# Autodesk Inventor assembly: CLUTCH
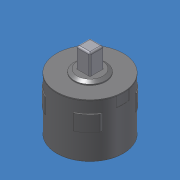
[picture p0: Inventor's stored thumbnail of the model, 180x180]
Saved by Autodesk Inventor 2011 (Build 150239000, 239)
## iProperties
Created: 2007-08
Part Number: CLUTCH
Document SubType Name: Assembly
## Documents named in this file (3)
- C:\Data Folder\VEX 2011\Inventor Datasets\Unit 6\Components\CLUTCH.iam
- C:\Data Folder\VEX 2011\Inventor Datasets\Unit 6\Components\Clutch Body.ipt
- C:\Data Folder\VEX 2011\Inventor Datasets\Unit 6\Components\Clutch Axle.ipt
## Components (2 placed, 2 different names)
1. Clutch Body:1 — Mate:1, Mate:2, Mate:3
2. Clutch Axle:1 — Mate:1, Mate:2, Mate:3
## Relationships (3: Mate 3)
- Mate:1: Clutch Body:1 ↔ Clutch Axle:1
- Mate:2: Clutch Body:1 ↔ Clutch Axle:1
- Mate:3: Clutch Body:1 ↔ Clutch Axle:1
